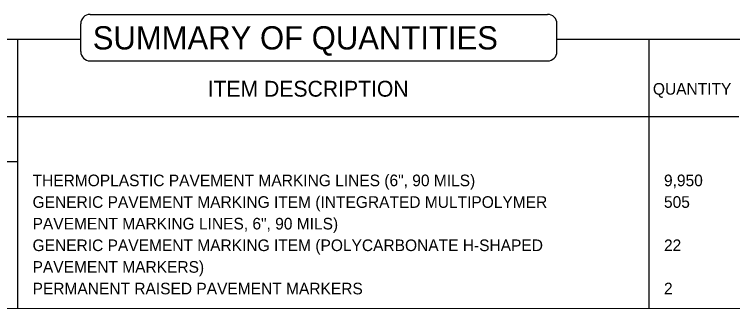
# Model space of a CAD drawing. Extents: x -63 to 3072, y 0 to 1100.
# Drawn here: x 413.8 to 822.3, y 347.2 to 514.3 of the extents above; entities that cross this region are included whole.
import ezdxf

# ---------------------------------------------------------------- set-up
doc = ezdxf.new("R2010")
doc.units = 0
for name, color, linetype in [('Sheet Data Text CELL', 7, 'Continuous'), ('Sheet_Data_Field_CELL', 7, 'Continuous'), ('Sheet_RDY_PE_Seal_Cell', 7, 'Continuous')]:
    doc.layers.add(name, color=color, linetype=linetype)

msp = doc.modelspace()

# ---------------------------------------------------------------- linework, layer by layer
at = {"layer": 'Sheet_RDY_PE_Seal_Cell'}
for p, q in [((451.56, 493.23), (451.56, 508.94)), ((722.41, 493.23), (722.41, 508.94)), ((297.1, 500.34), (451.56, 500.25)), ((415.71, 347.34), (415.73, 500.27)), ((722.42, 500.28), (848.75, 500.12)), ((774.82, 347.2), (774.85, 500.22)), ((288.17, 456.28), (774.84, 456.28)), ((774.84, 456.28), (825.85, 456.28)), ((288.16, 430.7), (415.72, 430.7)), ((297, 347.39), (848.65, 347.17))]:
    msp.add_line(p, q, dxfattribs=at)
for points in [[(456.9, 514.28), (717.07, 514.28)], [(456.91, 487.88), (717.07, 487.88)]]:
    msp.add_lwpolyline(points, dxfattribs=at)
for centre, start, end in [((456.9, 508.94), 90.0066, 180.0066), ((717.07, 508.94), 0.0066, 90.0066), ((456.9, 493.23), 180.0066, 270.0066), ((717.07, 493.23), 270.0066, 0.0066)]:
    msp.add_arc(centre, 5.35, start, end, dxfattribs=at)

# ---------------------------------------------------------------- texts
at = {"layer": 'Sheet Data Text CELL'}
msp.add_text('SUMMARY OF QUANTITIES', height=13.2, rotation=360, dxfattribs=at).set_placement((458.36, 494.36))
at = {"layer": 'Sheet_Data_Field_CELL'}
for s, height, p in [('ITEM DESCRIPTION', 9, (523.7, 467.55)), ('QUANTITY', 6.6, (776.98, 468.68)), ('THERMOPLASTIC PAVEMENT MARKING LINES (6", 90 MILS)', 6.6, (424.14, 416.69)), ('9,950', 6.6, (783.28, 416.7)), ('GENERIC PAVEMENT MARKING ITEM (INTEGRATED MULTIPOLYMER', 6.6, (424.14, 404.4)), ('505', 6.6, (783.28, 404.41)), ('PAVEMENT MARKING LINES, 6", 90 MILS)', 6.6, (424.14, 392.12)), ('GENERIC PAVEMENT MARKING ITEM (POLYCARBONATE H-SHAPED', 6.6, (424.14, 379.84)), ('22', 6.6, (783.28, 379.85)), ('PAVEMENT MARKERS)', 6.6, (424.14, 367.56)), ('PERMANENT RAISED PAVEMENT MARKERS', 6.6, (424.14, 355.27)), ('2', 6.6, (783.28, 355.28))]:
    msp.add_text(s, height=height, dxfattribs=at).set_placement(p)

doc.saveas('drawing.dxf')
